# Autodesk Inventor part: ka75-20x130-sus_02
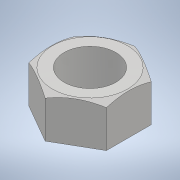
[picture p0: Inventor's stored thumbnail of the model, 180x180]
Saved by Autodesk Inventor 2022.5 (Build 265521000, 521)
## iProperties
Part Number: ka75-20x130-sus_02
Material: 一般
Document SubType Name: Modeling
Designer: ImaoCorp
Density: 1 g/cm^3
Appearance: 既定
Author: ImaoCorp
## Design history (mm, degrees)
feature "ka75-20x130-sus_02"
node "ソリッド1"
